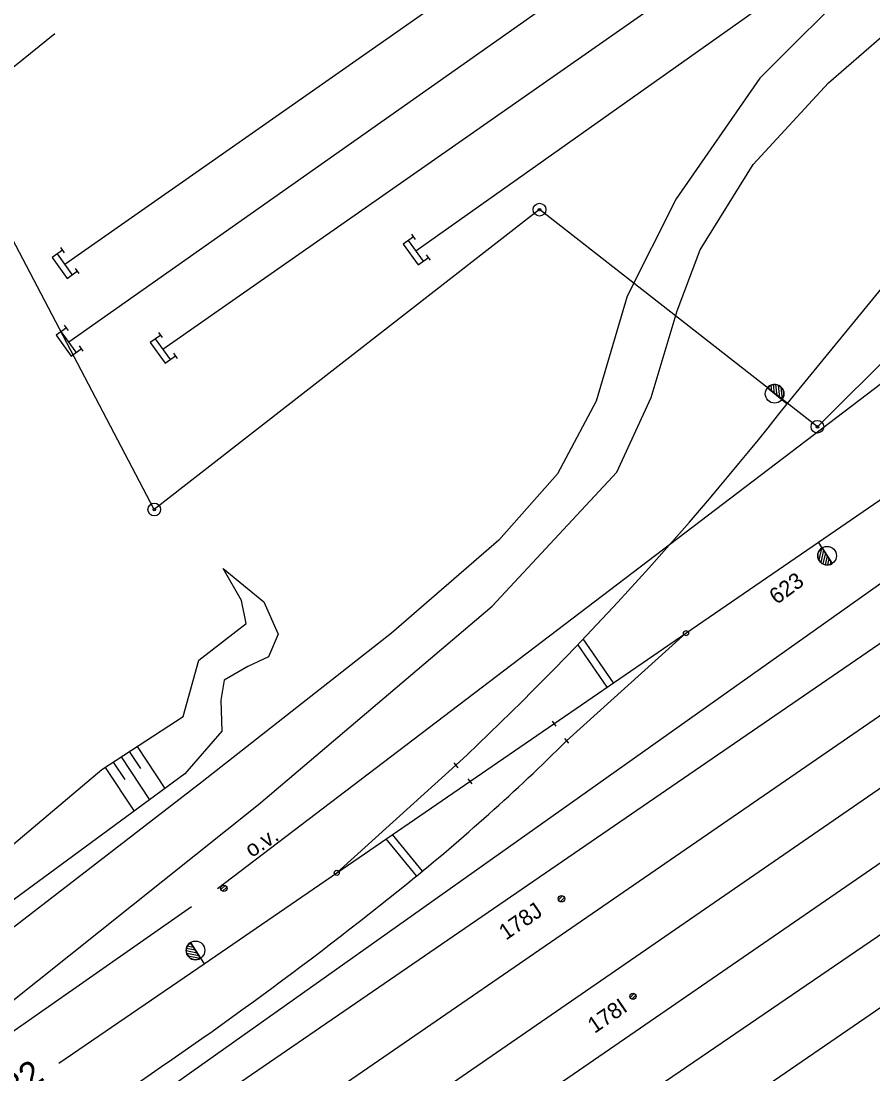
# Model space of a CAD drawing. Extents: x -469926 to -462499, y -1098642 to -1092733.
# Drawn here: x -467205.6 to -467138.8, y -1096585.9 to -1096503.3 of the extents above; entities that cross this region are included whole.
import ezdxf

# ---------------------------------------------------------------- set-up
doc = ezdxf.new("R2010")
doc.units = 0
for name, color, linetype in [('Vrstva 1', 7, 'Continuous'), ('Vrstva 11', 7, 'Continuous'), ('Vrstva 13', 7, 'Continuous'), ('Vrstva 24', 7, 'Continuous'), ('Vrstva 48', 7, 'Continuous'), ('Vrstva 50', 7, 'Continuous'), ('Vrstva 51', 7, 'Continuous'), ('Vrstva 52', 7, 'Continuous'), ('Vrstva 6', 7, 'Continuous'), ('Vrstva 62', 7, 'Continuous'), ('Vrstva 7', 7, 'Continuous'), ('Vrstva 8', 7, 'Continuous')]:
    doc.layers.add(name, color=color, linetype=linetype)

msp = doc.modelspace()

# ---------------------------------------------------------------- linework, layer by layer
at = {"layer": 'Vrstva 1'}
for p, q in [((-467195.17, -1096541.65), (-467227.98, -1096479.14)), ((-467115, -1096507.13), (-467143.15, -1096535.16)), ((-467145.529, -1096533.35), (-467129.571, -1096513.862)), ((-467164.95, -1096518.13), (-467195.17, -1096541.65)), ((-467143.15, -1096535.16), (-467164.95, -1096518.13)), ((-467162.828, -1096559.796), (-467153.459, -1096551.351))]:
    msp.add_line(p, q, dxfattribs=at)
for points in [[(-467194.491, -1096529.071), (-467129.633, -1096483.74), (-467127.146, -1096481.989), (-467084.774, -1096452.432), (-466913.12, -1096332.641), (-466892.399, -1096318.214), (-466875.922, -1096306.749), (-466855.977, -1096293.264)], [(-467174.648, -1096521.363), (-467126.609, -1096487.357), (-467124.106, -1096485.599), (-467081.847, -1096456.236), (-466889.627, -1096322.74), (-466872.862, -1096311.103), (-466853.227, -1096297.291)], [(-467202.186, -1096522.415), (-467136.509, -1096476.407), (-467134.001, -1096474.634), (-467091.245, -1096444.747), (-467032.17, -1096403.456), (-466961.905, -1096354.439), (-466898.173, -1096310.019), (-466881.685, -1096298.64)], [(-467201.88, -1096528.506), (-467132.869, -1096479.894), (-467130.379, -1096478.145), (-467088.014, -1096448.351), (-467030.192, -1096407.704), (-466959.432, -1096357.982), (-466895.955, -1096313.329), (-466879.472, -1096301.771)], [(-467202.668, -1096585.07), (-467191.257, -1096577.279), (-467180.857, -1096570.146), (-467170.411, -1096562.981), (-467163.815, -1096558.455), (-467153.459, -1096551.351), (-467143.059, -1096544.218), (-467134.372, -1096538.261), (-467123.974, -1096531.125), (-467113.607, -1096524.01), (-467103.217, -1096516.862), (-467092.773, -1096509.677)], [(-467197.601, -1096592.878), (-467187.975, -1096586.246), (-467136.083, -1096550.672), (-467123.31, -1096542.169), (-467105.77, -1096530.09)], [(-467194.911, -1096596.782), (-467185.386, -1096590.225), (-467132.163, -1096553.619), (-467119.664, -1096545.287), (-467101.602, -1096532.972)], [(-467192.196, -1096600.722), (-467181.87, -1096593.577), (-467128.699, -1096556.945), (-467117.184, -1096549.326), (-467100.234, -1096537.665)], [(-467184.206, -1096612.315), (-467172.852, -1096604.487), (-467120.759, -1096568.747), (-467108.181, -1096560.271), (-467088.958, -1096547.035), (-467083.737, -1096543.464)], [(-467189.499, -1096604.635), (-467179.259, -1096597.59), (-467125.572, -1096560.67), (-467114.526, -1096553.274), (-467101.626, -1096544.36)], [(-467186.939, -1096608.35), (-467175.49, -1096600.432), (-467110.839, -1096556.308), (-467096.857, -1096546.66)]]:
    msp.add_lwpolyline(points, dxfattribs=at)
for centre, radius, start, end in [((-467346.876, -1096375.02), 256.143, 313.20798, 321.81999), ((-467278.488, -1096443.203), 164.228, 308.93064, 314.76989), ((-467368.659, -1096331.575), 307.727, 303.19248, 308.93064)]:
    msp.add_arc(centre, radius, start, end, dxfattribs=at)
at = {"layer": 'Vrstva 11'}
for p, q in [((-467189.946, -1096571.457), (-467189.622, -1096571.134)), ((-467189.816, -1096571.592), (-467189.488, -1096571.264)), ((-467163.456, -1096572.275), (-467163.134, -1096571.952)), ((-467163.326, -1096572.41), (-467162.999, -1096572.082)), ((-467157.844, -1096579.928), (-467157.522, -1096579.605)), ((-467157.714, -1096580.063), (-467157.387, -1096579.736))]:
    msp.add_line(p, q, dxfattribs=at)
for centre in [(-467189.715, -1096571.365), (-467163.226, -1096572.183), (-467157.614, -1096579.836)]:
    msp.add_circle(centre, 0.25, dxfattribs=at)
at = {"layer": 'Vrstva 13'}
for points in [[(-467139.848, -1096500), (-467147.665, -1096507.818), (-467154.228, -1096517.286), (-467158.069, -1096524.925), (-467160.507, -1096533.164), (-467163.55, -1096538.841), (-467168.136, -1096544.054), (-467176.57, -1096551.342), (-467191.402, -1096563.018), (-467214.711, -1096580.962), (-467253.222, -1096606.148)], [(-467249.68, -1096611.217), (-467211.855, -1096584.6), (-467186.991, -1096564.775), (-467168.654, -1096549.232), (-467158.889, -1096538.729), (-467156.198, -1096532.877), (-467154.148, -1096526.058), (-467152.351, -1096521.288), (-467148.182, -1096514.593), (-467142.269, -1096508.194), (-467135.346, -1096502.176), (-467132.054, -1096500)]]:
    msp.add_lwpolyline(points, dxfattribs=at)
at = {"layer": 'Vrstva 24'}
for centre, radius in [((-467164.95, -1096518.13), 0.5), ((-467164.95, -1096518.13), 0.1), ((-467143.15, -1096535.16), 0.5), ((-467143.15, -1096535.16), 0.1), ((-467195.17, -1096541.65), 0.5), ((-467195.17, -1096541.65), 0.1)]:
    msp.add_circle(centre, radius, dxfattribs=at)
at = {"layer": 'Vrstva 48'}
for points in [[(-467197.129, -1096560.64), (-467196.255, -1096561.972)], [(-467196.502, -1096560.228), (-467194.339, -1096563.526)], [(-467198.384, -1096561.463), (-467197.491, -1096562.823)], [(-467197.757, -1096561.051), (-467195.548, -1096564.417)], [(-467199.011, -1096561.874), (-467196.757, -1096565.308)]]:
    msp.add_lwpolyline(points, dxfattribs=at)
at = {"layer": 'Vrstva 50'}
for p, q in [((-467163.243, -1096565.198), (-467108.814, -1096526.614)), ((-467222.906, -1096607.456), (-467163.243, -1096565.198))]:
    msp.add_line(p, q, dxfattribs=at)
at = {"layer": 'Vrstva 51'}
for p, q in [((-467190.215, -1096571.365), (-467114.417, -1096513.689)), ((-467272.363, -1096628.775), (-467192.252, -1096572.793))]:
    msp.add_line(p, q, dxfattribs=at)
at = {"layer": 'Vrstva 52'}
msp.add_line((-467332.054, -1096608.532), (-467202.967, -1096504.309), dxfattribs=at)
at = {"layer": 'Vrstva 6'}
msp.add_line((-467180.857, -1096570.146), (-467171.508, -1096561.715), dxfattribs=at)
at = {"layer": 'Vrstva 62'}
for p, q in [((-467174.68, -1096520.462), (-467174.972, -1096520.056)), ((-467174.064, -1096522.176), (-467175.232, -1096520.551)), ((-467201.602, -1096523.228), (-467202.77, -1096521.603)), ((-467202.218, -1096521.514), (-467202.51, -1096521.108)), ((-467174.648, -1096521.363), (-467174.648, -1096521.363)), ((-467173.512, -1096522.087), (-467173.804, -1096521.681)), ((-467202.186, -1096522.415), (-467202.186, -1096522.415)), ((-467201.05, -1096523.139), (-467201.342, -1096522.733)), ((-467201.912, -1096527.605), (-467202.204, -1096527.199)), ((-467201.296, -1096529.319), (-467202.464, -1096527.694)), ((-467193.907, -1096529.884), (-467195.075, -1096528.259)), ((-467194.523, -1096528.17), (-467194.815, -1096527.764)), ((-467201.88, -1096528.506), (-467201.88, -1096528.506)), ((-467200.744, -1096529.23), (-467201.036, -1096528.824)), ((-467194.491, -1096529.071), (-467194.491, -1096529.071)), ((-467193.355, -1096529.795), (-467193.647, -1096529.389)), ((-467159.649, -1096555.597), (-467161.946, -1096552.248)), ((-467159.154, -1096555.258), (-467161.522, -1096551.805)), ((-467174.131, -1096570.013), (-467176.482, -1096567.145)), ((-467174.595, -1096570.393), (-467176.979, -1096567.486))]:
    msp.add_line(p, q, dxfattribs=at)
for points in [[(-467174.826, -1096520.259), (-467175.638, -1096520.843), (-467174.47, -1096522.468), (-467173.658, -1096521.884)], [(-467202.364, -1096521.311), (-467203.176, -1096521.895), (-467202.008, -1096523.52), (-467201.196, -1096522.936)], [(-467202.058, -1096527.402), (-467202.87, -1096527.986), (-467201.702, -1096529.611), (-467200.89, -1096529.027)], [(-467194.669, -1096527.967), (-467195.481, -1096528.551), (-467194.313, -1096530.176), (-467193.501, -1096529.592)], [(-467214.295, -1096574.693), (-467199.28, -1096562.051), (-467192.913, -1096557.873), (-467191.672, -1096553.476), (-467187.964, -1096550.599), (-467188.332, -1096548.787), (-467189.764, -1096546.273), (-467186.575, -1096548.884), (-467185.445, -1096551.428), (-467186.202, -1096553.196), (-467187.843, -1096553.954), (-467189.682, -1096555.031), (-467189.952, -1096556.614), (-467189.863, -1096559.024), (-467192.775, -1096562.374), (-467207.025, -1096572.873)]]:
    msp.add_lwpolyline(points, dxfattribs=at)
at = {"layer": 'Vrstva 8'}
for p, q in [((-467145.932, -1096533.031), (-467147.076, -1096532.119)), ((-467147.076, -1096532.119), (-467145.932, -1096533.031)), ((-467146.928, -1096532.237), (-467146.955, -1096532)), ((-467146.72, -1096532.402), (-467146.778, -1096531.898)), ((-467146.513, -1096532.567), (-467146.594, -1096531.85)), ((-467146.306, -1096532.734), (-467146.406, -1096531.851)), ((-467146.098, -1096532.899), (-467146.211, -1096531.905)), ((-467145.9, -1096532.984), (-467146.006, -1096532.041)), ((-467145.932, -1096533.031), (-467145.529, -1096533.35)), ((-467145.932, -1096533.031), (-467145.932, -1096533.031)), ((-467142.782, -1096544.652), (-467143.059, -1096544.218)), ((-467142.828, -1096544.686), (-467143.035, -1096545.612)), ((-467142.668, -1096544.831), (-467142.887, -1096545.807)), ((-467142.782, -1096544.652), (-467141.999, -1096545.888)), ((-467142.782, -1096544.652), (-467142.782, -1096544.652)), ((-467141.999, -1096545.888), (-467142.782, -1096544.652)), ((-467142.526, -1096545.055), (-467142.72, -1096545.922)), ((-467142.385, -1096545.28), (-467142.542, -1096545.984)), ((-467142.243, -1096545.503), (-467142.353, -1096545.999)), ((-467142.1, -1096545.728), (-467142.152, -1096545.96)), ((-467153.459, -1096551.351), (-467153.46, -1096551.351)), ((-467163.966, -1096558.257), (-467163.664, -1096558.653)), ((-467162.989, -1096559.604), (-467162.667, -1096559.988)), ((-467171.664, -1096561.52), (-467171.352, -1096561.91)), ((-467170.562, -1096562.782), (-467170.26, -1096563.18)), ((-467180.857, -1096570.146), (-467180.858, -1096570.146)), ((-467191.798, -1096576.447), (-467192.667, -1096576.264)), ((-467191.943, -1096576.225), (-467192.65, -1096576.076)), ((-467192.088, -1096576.003), (-467192.585, -1096575.898)), ((-467192.233, -1096575.781), (-467192.466, -1096575.731)), ((-467191.537, -1096576.847), (-467192.337, -1096575.621)), ((-467192.337, -1096575.621), (-467191.537, -1096576.847)), ((-467191.653, -1096576.669), (-467192.631, -1096576.463)), ((-467191.587, -1096576.874), (-467192.516, -1096576.679)), ((-467191.537, -1096576.847), (-467191.257, -1096577.279)), ((-467191.537, -1096576.847), (-467191.537, -1096576.847))]:
    msp.add_line(p, q, dxfattribs=at)
for centre, radius in [((-467146.507, -1096532.571), 0.731), ((-467142.389, -1096545.274), 0.731), ((-467153.459, -1096551.351), 0.2), ((-467180.857, -1096570.146), 0.2), ((-467191.939, -1096576.231), 0.731)]:
    msp.add_circle(centre, radius, dxfattribs=at)
for centre, start, end in [((-467146.505, -1096532.575), 321.48199, 141.44284), ((-467142.39, -1096545.27), 122.4033, 302.36415), ((-467191.937, -1096576.234), 123.12807, 303.08892)]:
    msp.add_arc(centre, 0.732, start, end, dxfattribs=at)

# ---------------------------------------------------------------- texts
at = {"layer": 'Vrstva 11'}
for s, p in [('178J', (-467167.587, -1096575.474)), ('178I', (-467160.627, -1096582.786))]:
    msp.add_text(s, height=1.25, rotation=34.56925, dxfattribs=at).set_placement(p)
at = {"layer": 'Vrstva 62'}
for s, height, rotation, p in [('623', 1.25, 36.3268, (-467146.342, -1096549.149)), ('632', 2, 35.2176, (-467207.339, -1096588.895))]:
    msp.add_text(s, height=height, rotation=rotation, dxfattribs=at).set_placement(p)
at = {"layer": 'Vrstva 7'}
msp.add_text('o.v.', height=1.25, rotation=33.42764, dxfattribs=at).set_placement((-467187.533, -1096568.991))

doc.saveas('drawing.dxf')
